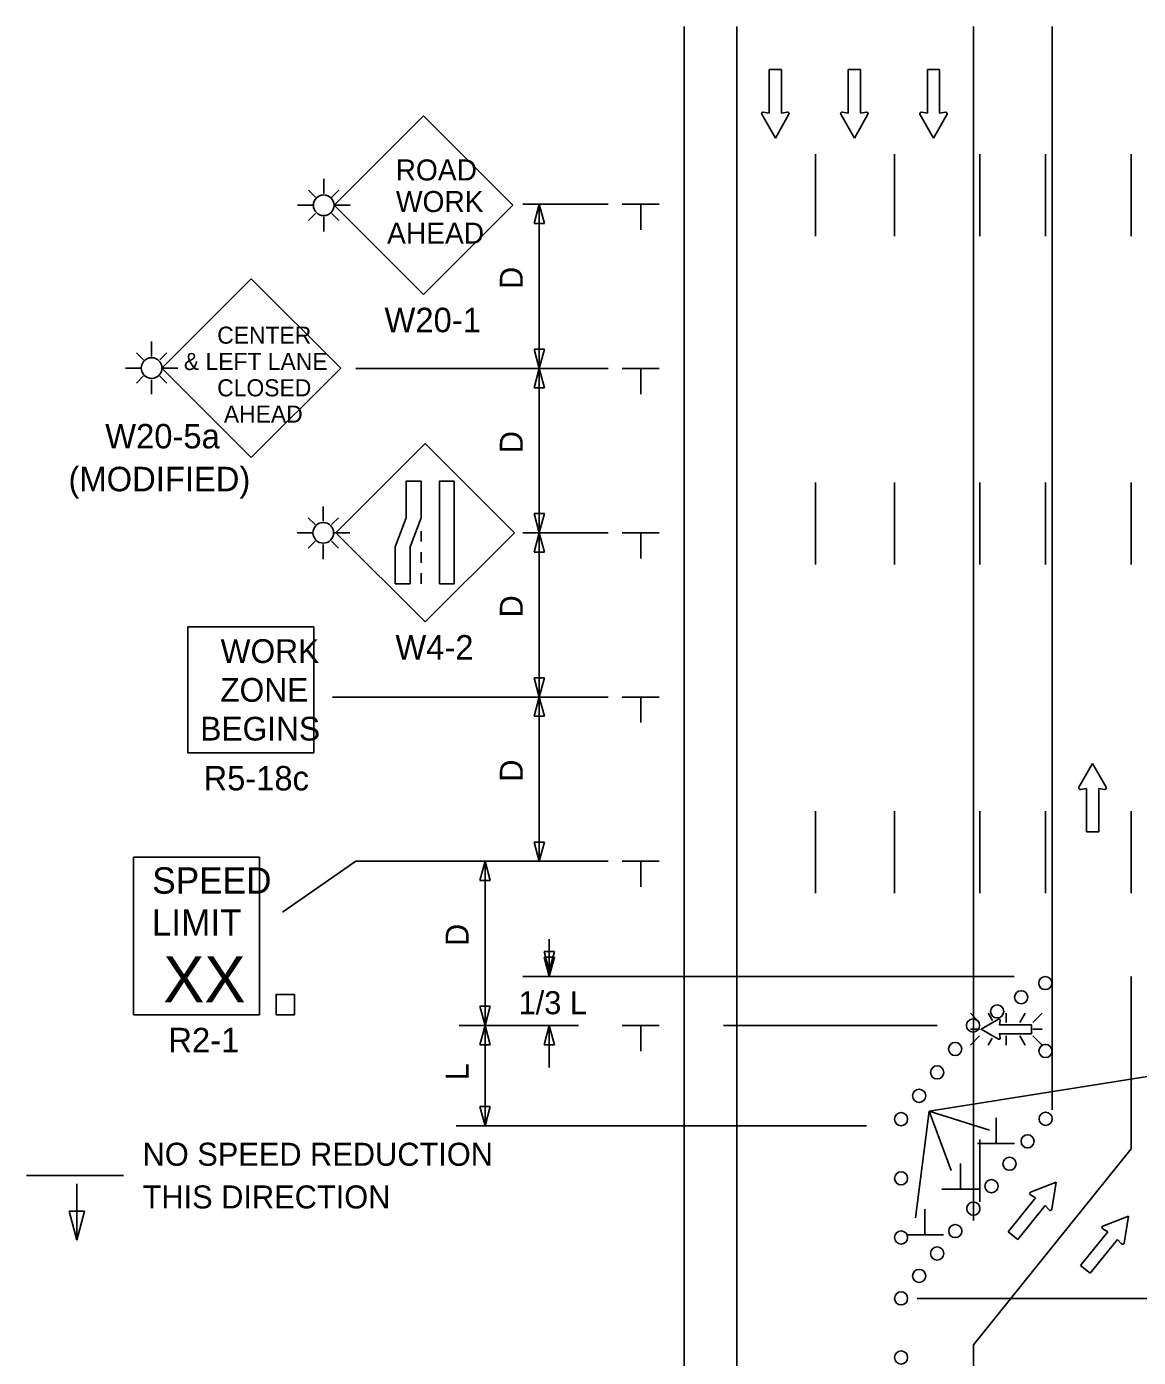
# Model space of a CAD drawing. Extents: x 16544 to 19504, y 5662 to 6922.
# Drawn here: x 16723.4 to 17061.7, y 6474.9 to 6880 of the extents above; entities that cross this region are included whole.
import ezdxf

# ---------------------------------------------------------------- set-up
doc = ezdxf.new("R2010")
doc.units = 0
for name, color, linetype in [('ALI_LEGAL_EX', 7, 'Continuous'), ('Level 3', 7, 'Continuous'), ('MT_SCRATCH_LEVEL_E', 7, 'Continuous'), ('PAVT_EDGE_EX', 7, 'Continuous'), ('TRAFFIC_SIGNS_PR', 7, 'Continuous'), ('TYPICAL_TEXT_DIMEN_PR', 7, 'Continuous')]:
    doc.layers.add(name, color=color, linetype=linetype)

msp = doc.modelspace()

# ---------------------------------------------------------------- linework, layer by layer
at = {"layer": 'ALI_LEGAL_EX'}
for points in [[(16963.46, 6841.23), (16963.46, 6816.23)], [(16987.46, 6841.23), (16987.46, 6816.23)], [(17013.46, 6841.23), (17013.46, 6816.23)], [(17033.46, 6841.23), (17033.46, 6816.23)], [(17059.46, 6841.23), (17059.46, 6816.23)], [(16963.46, 6741.23), (16963.46, 6716.23)], [(16987.46, 6741.23), (16987.46, 6716.23)], [(16987.46, 6741.23), (16987.46, 6716.23)], [(17013.46, 6741.23), (17013.46, 6716.23)], [(17013.46, 6741.23), (17013.46, 6716.23)], [(17033.46, 6741.23), (17033.46, 6716.23)], [(17033.46, 6741.23), (17033.46, 6716.23)], [(17059.46, 6741.23), (17059.46, 6716.23)], [(17059.46, 6741.23), (17059.46, 6716.23)], [(16963.46, 6641.23), (16963.46, 6616.23)], [(16987.46, 6641.23), (16987.46, 6616.23)], [(16987.46, 6641.23), (16987.46, 6616.23)], [(17013.46, 6641.23), (17013.46, 6616.23)], [(17013.46, 6641.23), (17013.46, 6616.23)], [(17033.46, 6641.23), (17033.46, 6616.23)], [(17033.46, 6641.23), (17033.46, 6616.23)], [(17059.46, 6641.23), (17059.46, 6616.23)], [(17059.46, 6641.23), (17059.46, 6616.23)], [(17013.46, 6541.23), (17013.46, 6522.22)], [(17013.46, 6541.23), (17013.46, 6524.21)]]:
    msp.add_lwpolyline(points, dxfattribs=at)
at = {"layer": 'Level 3'}
for p, q in [((16823.56, 6625.93), (16801.21, 6610.49)), ((16882.4, 6602.19), (16882.4, 6590.85)), ((16882.4, 6575.93), (16882.4, 6563.15))]:
    msp.add_line(p, q, dxfattribs=at)
at = {"layer": 'MT_SCRATCH_LEVEL_E'}
for p, q in [((16953.06, 6866.95), (16949.32, 6866.95)), ((16949.32, 6866.95), (16949.32, 6853.69)), ((16953.06, 6866.95), (16949.32, 6866.95)), ((16949.32, 6866.95), (16949.32, 6853.69)), ((16953.06, 6853.69), (16953.06, 6866.95)), ((16953.06, 6853.69), (16953.06, 6866.95)), ((16977.13, 6866.95), (16973.39, 6866.95)), ((16973.39, 6866.95), (16973.39, 6853.69)), ((16977.13, 6866.95), (16973.39, 6866.95)), ((16973.39, 6866.95), (16973.39, 6853.69)), ((16977.13, 6853.69), (16977.13, 6866.95)), ((16977.13, 6853.69), (16977.13, 6866.95)), ((17001.2, 6866.95), (16997.46, 6866.95)), ((16997.46, 6866.95), (16997.46, 6853.69)), ((17001.2, 6866.95), (16997.46, 6866.95)), ((16997.46, 6866.95), (16997.46, 6853.69)), ((17001.2, 6853.69), (17001.2, 6866.95)), ((17001.2, 6853.69), (17001.2, 6866.95)), ((16947.06, 6853.32), (16951.21, 6846.09)), ((16947.06, 6853.32), (16951.21, 6846.09)), ((16949.32, 6853.69), (16947.54, 6854.01)), ((16949.32, 6853.69), (16947.54, 6854.01)), ((16951.21, 6846.09), (16955.32, 6853.32)), ((16951.21, 6846.09), (16955.32, 6853.32)), ((16954.83, 6854.01), (16953.06, 6853.69)), ((16954.83, 6854.01), (16953.06, 6853.69)), ((16971.13, 6853.32), (16975.28, 6846.09)), ((16971.13, 6853.32), (16975.28, 6846.09)), ((16973.39, 6853.69), (16971.61, 6854.01)), ((16973.39, 6853.69), (16971.61, 6854.01)), ((16975.28, 6846.09), (16979.39, 6853.32)), ((16975.28, 6846.09), (16979.39, 6853.32)), ((16978.91, 6854.01), (16977.13, 6853.69)), ((16978.91, 6854.01), (16977.13, 6853.69)), ((16995.2, 6853.32), (16999.35, 6846.09)), ((16995.2, 6853.32), (16999.35, 6846.09)), ((16997.46, 6853.69), (16995.68, 6854.01)), ((16997.46, 6853.69), (16995.68, 6854.01)), ((16999.35, 6846.09), (17003.46, 6853.32)), ((16999.35, 6846.09), (17003.46, 6853.32)), ((17002.98, 6854.01), (17001.2, 6853.69)), ((17002.98, 6854.01), (17001.2, 6853.69)), ((17047.7, 6655.73), (17043.59, 6648.49)), ((17047.7, 6655.73), (17043.59, 6648.49)), ((17051.85, 6648.49), (17047.7, 6655.73)), ((17051.85, 6648.49), (17047.7, 6655.73)), ((17044.07, 6647.81), (17045.85, 6648.12)), ((17044.07, 6647.81), (17045.85, 6648.12)), ((17045.85, 6648.12), (17045.85, 6634.86)), ((17045.85, 6648.12), (17045.85, 6634.86)), ((17049.59, 6634.86), (17049.59, 6648.12)), ((17049.59, 6648.12), (17051.37, 6647.81)), ((17049.59, 6634.86), (17049.59, 6648.12)), ((17049.59, 6648.12), (17051.37, 6647.81)), ((17045.85, 6634.86), (17049.59, 6634.86)), ((17045.85, 6634.86), (17049.59, 6634.86)), ((17028.87, 6525.2), (17036.64, 6528.24)), ((17028.87, 6525.2), (17036.64, 6528.24)), ((17036.64, 6528.24), (17035.3, 6520.02)), ((17036.64, 6528.24), (17035.3, 6520.02)), ((17022.08, 6513.17), (17030.39, 6523.5)), ((17022.08, 6513.17), (17030.39, 6523.5)), ((17030.39, 6523.5), (17028.81, 6524.37)), ((17030.39, 6523.5), (17028.81, 6524.37)), ((17033.31, 6521.15), (17024.99, 6510.82)), ((17033.31, 6521.15), (17024.99, 6510.82)), ((17034.49, 6519.79), (17033.31, 6521.15)), ((17034.49, 6519.79), (17033.31, 6521.15)), ((17050.89, 6514.87), (17058.66, 6517.91)), ((17050.89, 6514.87), (17058.66, 6517.91)), ((17058.66, 6517.91), (17057.32, 6509.69)), ((17058.66, 6517.91), (17057.32, 6509.69)), ((17024.99, 6510.82), (17022.08, 6513.17)), ((17024.99, 6510.82), (17022.08, 6513.17)), ((17044.1, 6502.84), (17052.41, 6513.17)), ((17044.1, 6502.84), (17052.41, 6513.17)), ((17055.33, 6510.82), (17047.01, 6500.5)), ((17055.33, 6510.82), (17047.01, 6500.5)), ((17052.41, 6513.17), (17050.83, 6514.04)), ((17052.41, 6513.17), (17050.83, 6514.04)), ((17056.51, 6509.46), (17055.33, 6510.82)), ((17056.51, 6509.46), (17055.33, 6510.82)), ((17047.01, 6500.5), (17044.1, 6502.84)), ((17047.01, 6500.5), (17044.1, 6502.84))]:
    msp.add_line(p, q, dxfattribs=at)
for centre, start, end in [((16947.47, 6853.55), 80.0362, 209.7731), ((16947.47, 6853.55), 80.0362, 209.7731), ((16954.91, 6853.55), 330.4248, 99.9638), ((16954.91, 6853.55), 330.4248, 99.9638), ((16971.54, 6853.55), 80.0362, 209.7731), ((16971.54, 6853.55), 80.0362, 209.7731), ((16978.98, 6853.55), 330.4248, 99.9638), ((16978.98, 6853.55), 330.4248, 99.9638), ((16995.61, 6853.55), 80.0362, 209.7731), ((16995.61, 6853.55), 80.0362, 209.7731), ((17003.05, 6853.55), 330.4248, 99.9638), ((17003.05, 6853.55), 330.4248, 99.9638), ((17044, 6648.26), 150.4248, 279.9638), ((17044, 6648.26), 150.4248, 279.9638), ((17051.44, 6648.27), 260.0362, 29.7731), ((17051.44, 6648.27), 260.0362, 29.7731), ((17029.04, 6524.77), 111.3861, 241.123), ((17029.04, 6524.77), 111.3861, 241.123), ((17034.84, 6520.1), 221.1954, 350.7344), ((17034.84, 6520.1), 221.1954, 350.7344), ((17051.06, 6514.44), 111.3861, 241.123), ((17051.06, 6514.44), 111.3861, 241.123), ((17056.86, 6509.77), 221.1954, 350.7344), ((17056.86, 6509.77), 221.1954, 350.7344)]:
    msp.add_arc(centre, 0.463, start, end, dxfattribs=at)
at = {"layer": 'PAVT_EDGE_EX'}
for p, q in [((16923.46, 6880.02), (16923.46, 6074.05)), ((16939.46, 6880.02), (16939.46, 6074.05)), ((17011.46, 6880.02), (17011.46, 6516.57)), ((17035.46, 6880.02), (17035.46, 6550.27)), ((17011.46, 6794.72), (17011.46, 6522.22)), ((17035.46, 6794.72), (17035.46, 6552.57)), ((17059.46, 6590.85), (17059.46, 6538.35)), ((17011.46, 6478.73), (17059.46, 6538.35)), ((17011.46, 6478.73), (17011.46, 6277.01))]:
    msp.add_line(p, q, dxfattribs=at)
at = {"layer": 'TRAFFIC_SIGNS_PR'}
for p, q in [((16844.12, 6852.82), (16816.94, 6825.63)), ((16871.31, 6825.63), (16844.12, 6852.82)), ((16813.78, 6829.19), (16813.78, 6833.69)), ((16811.27, 6828.15), (16809.16, 6830.25)), ((16816.3, 6828.15), (16818.41, 6830.25)), ((16810.63, 6825.63), (16805.79, 6825.63)), ((16811.27, 6823.12), (16809.16, 6821.01)), ((16816.3, 6823.12), (16818.4, 6821.01)), ((16816.94, 6825.63), (16821.82, 6825.63)), ((16816.94, 6825.63), (16844.12, 6798.45)), ((16844.12, 6798.45), (16871.31, 6825.63)), ((16813.78, 6817.67), (16813.78, 6822.08)), ((16791.76, 6803.27), (16764.57, 6776.08)), ((16818.95, 6776.08), (16791.76, 6803.27)), ((16761.42, 6779.63), (16761.42, 6784.14)), ((16758.91, 6778.59), (16756.8, 6780.7)), ((16763.93, 6778.59), (16766.04, 6780.7)), ((16758.26, 6776.08), (16753.43, 6776.08)), ((16758.9, 6773.57), (16756.8, 6771.46)), ((16763.93, 6773.57), (16766.04, 6771.46)), ((16764.57, 6776.08), (16769.45, 6776.08)), ((16764.57, 6776.08), (16791.76, 6748.89)), ((16791.76, 6748.89), (16818.95, 6776.08)), ((16761.42, 6768.11), (16761.42, 6772.52)), ((16844.64, 6753.09), (16817.48, 6725.94)), ((16871.79, 6725.94), (16844.64, 6753.09)), ((16813.65, 6729.46), (16813.65, 6733.96)), ((16811.14, 6728.42), (16809.03, 6730.53)), ((16816.16, 6728.42), (16818.27, 6730.53)), ((16810.5, 6725.91), (16805.66, 6725.91)), ((16816.8, 6725.91), (16821.69, 6725.91)), ((16817.48, 6725.94), (16844.64, 6698.78)), ((16843.39, 6726.43), (16843.39, 6723.23)), ((16844.64, 6698.78), (16871.79, 6725.94)), ((16811.14, 6723.39), (16809.03, 6721.28)), ((16813.65, 6717.94), (16813.65, 6722.35)), ((16816.16, 6723.39), (16818.27, 6721.29)), ((16843.39, 6720.03), (16843.39, 6716.83)), ((16843.39, 6713.63), (16843.39, 6710.43)), ((16772.41, 6658.94), (16772.41, 6697.34)), ((16772.41, 6697.34), (16810.81, 6697.34)), ((16810.81, 6658.94), (16810.81, 6697.34)), ((16772.41, 6658.94), (16810.81, 6658.94)), ((16755.86, 6627.23), (16794.26, 6627.23)), ((16755.86, 6579.23), (16755.86, 6627.23)), ((16794.26, 6579.23), (16794.26, 6627.23)), ((16755.86, 6579.23), (16794.26, 6579.23)), ((17010.54, 6579.66), (17013.36, 6576.84)), ((17017.26, 6577.48), (17016, 6579.66)), ((17021.45, 6576.84), (17021.45, 6579.66)), ((17025.58, 6576.84), (17027.21, 6579.66)), ((17029.53, 6576.84), (17032.35, 6579.66)), ((17013.36, 6574.81), (17010.54, 6574.81)), ((17010.54, 6569.96), (17013.36, 6572.78)), ((17015.98, 6569.96), (17017.19, 6572.05)), ((17021.45, 6572.78), (17021.45, 6569.96)), ((17027.24, 6569.96), (17025.61, 6572.78)), ((17029.53, 6574.81), (17032.35, 6574.81)), ((17029.53, 6572.78), (17032.35, 6569.96))]:
    msp.add_line(p, q, dxfattribs=at)
for points in [[(16843.39, 6741.67), (16843.39, 6730.49), (16840.05, 6721.61), (16840.05, 6710.43), (16835.55, 6710.43), (16835.55, 6721.61), (16838.9, 6730.49), (16838.9, 6741.67)], [(16853.53, 6741.67), (16853.53, 6710.43), (16849.03, 6710.43), (16849.03, 6741.67)], [(16799.27, 6579.23), (16804.87, 6579.23), (16804.87, 6585.4), (16799.27, 6585.4)]]:
    msp.add_lwpolyline(points, close=True, dxfattribs=at)
for points in [[(17019.12, 6577.82), (17013.81, 6574.81), (17019.12, 6571.77)], [(17019.62, 6572.13), (17019.39, 6573.42), (17029.11, 6573.42), (17029.11, 6576.17), (17019.39, 6576.17), (17019.62, 6577.47)]]:
    msp.add_lwpolyline(points, dxfattribs=at)
for centre, radius in [((16813.78, 6825.63), 3.15), ((16761.42, 6776.08), 3.15), ((16813.65, 6725.91), 3.15), ((17033.35, 6588.85), 2), ((17033.35, 6588.85), 2), ((17026.02, 6584.54), 2), ((17018.69, 6580.23), 2), ((17011.36, 6575.93), 2), ((17005.94, 6568.79), 2), ((17033.4, 6568.18), 2), ((17000.45, 6561.67), 2), ((16994.95, 6554.54), 2), ((16989.46, 6547.41), 2), ((16989.46, 6547.41), 2), ((16989.46, 6547.41), 2), ((17033.46, 6547.51), 2), ((17027.96, 6540.68), 2), ((17022.46, 6533.85), 2), ((16989.46, 6529.41), 2), ((17016.96, 6527.02), 2), ((17011.46, 6520.19), 2), ((17005.96, 6513.36), 2), ((16989.46, 6511.41), 2), ((17000.46, 6506.53), 2), ((16994.96, 6499.7), 2), ((16989.46, 6492.87), 2), ((16989.46, 6474.87), 2)]:
    msp.add_circle(centre, radius, dxfattribs=at)
for centre, start, end in [((17019.28, 6577.53), 350.7308, 118.8916), ((17019.28, 6572.07), 241.4833, 9.9593)]:
    msp.add_arc(centre, 0.341, start, end, dxfattribs=at)
at = {"layer": 'TYPICAL_TEXT_DIMEN_PR'}
for p, q in [((16874.36, 6825.93), (16900.36, 6825.93)), ((16877.79, 6820.07), (16879.36, 6825.93)), ((16879.36, 6775.93), (16879.36, 6825.93)), ((16879.36, 6825.93), (16880.93, 6820.07)), ((16904.61, 6825.93), (16915.86, 6825.93)), ((16910.24, 6825.93), (16910.24, 6818.15)), ((16879.36, 6820.07), (16877.79, 6820.07)), ((16880.93, 6820.07), (16879.36, 6820.07)), ((16879.36, 6775.93), (16877.79, 6781.79)), ((16877.79, 6781.79), (16879.36, 6781.79)), ((16879.36, 6781.79), (16880.93, 6781.79)), ((16880.93, 6781.79), (16879.36, 6775.93)), ((16823.56, 6775.93), (16900.36, 6775.93)), ((16874.36, 6775.93), (16900.36, 6775.93)), ((16877.79, 6770.07), (16879.36, 6775.93)), ((16879.36, 6725.93), (16879.36, 6775.93)), ((16879.36, 6775.93), (16880.93, 6770.07)), ((16904.61, 6775.93), (16915.86, 6775.93)), ((16910.24, 6775.93), (16910.24, 6768.15)), ((16879.36, 6770.07), (16877.79, 6770.07)), ((16880.93, 6770.07), (16879.36, 6770.07)), ((16879.36, 6725.93), (16877.79, 6731.79)), ((16877.79, 6731.79), (16879.36, 6731.79)), ((16879.36, 6731.79), (16880.93, 6731.79)), ((16880.93, 6731.79), (16879.36, 6725.93)), ((16874.36, 6725.93), (16900.36, 6725.93)), ((16876.12, 6725.93), (16900.36, 6725.93)), ((16877.79, 6720.07), (16879.36, 6725.93)), ((16879.36, 6725.93), (16880.93, 6720.07)), ((16879.36, 6675.93), (16879.36, 6725.93)), ((16904.61, 6725.93), (16915.86, 6725.93)), ((16910.24, 6725.93), (16910.24, 6718.15)), ((16879.36, 6720.07), (16877.79, 6720.07)), ((16880.93, 6720.07), (16879.36, 6720.07)), ((16879.36, 6675.93), (16877.79, 6681.79)), ((16877.79, 6681.79), (16879.36, 6681.79)), ((16879.36, 6681.79), (16880.93, 6681.79)), ((16880.93, 6681.79), (16879.36, 6675.93)), ((16816.43, 6675.93), (16900.36, 6675.93)), ((16877.79, 6670.07), (16879.36, 6675.93)), ((16877.79, 6670.07), (16879.36, 6675.93)), ((16879.36, 6675.93), (16880.93, 6670.07)), ((16879.36, 6625.93), (16879.36, 6675.93)), ((16879.36, 6675.93), (16880.93, 6670.07)), ((16904.61, 6675.93), (16915.86, 6675.93)), ((16910.24, 6675.93), (16910.24, 6668.15)), ((16879.36, 6670.07), (16877.79, 6670.07)), ((16879.36, 6670.07), (16877.79, 6670.07)), ((16880.93, 6670.07), (16879.36, 6670.07)), ((16880.93, 6670.07), (16879.36, 6670.07)), ((16879.36, 6625.93), (16877.79, 6631.79)), ((16877.79, 6631.79), (16879.36, 6631.79)), ((16879.36, 6631.79), (16880.93, 6631.79)), ((16880.93, 6631.79), (16879.36, 6625.93)), ((16823.56, 6625.93), (16900.36, 6625.93)), ((16861.31, 6620.07), (16862.88, 6625.93)), ((16862.88, 6575.93), (16862.88, 6625.93)), ((16862.88, 6625.93), (16864.45, 6620.07)), ((16874.36, 6625.93), (16900.36, 6625.93)), ((16904.61, 6625.93), (16915.86, 6625.93)), ((16910.24, 6625.93), (16910.24, 6618.15)), ((16862.88, 6620.07), (16861.31, 6620.07)), ((16864.45, 6620.07), (16862.88, 6620.07)), ((16882.4, 6592.58), (16880.83, 6598.44)), ((16880.83, 6598.44), (16882.4, 6598.44)), ((16882.4, 6590.85), (16880.83, 6596.72)), ((16880.83, 6596.72), (16882.4, 6596.72)), ((16882.4, 6598.44), (16883.97, 6598.44)), ((16883.97, 6598.44), (16882.4, 6592.58)), ((16882.4, 6596.72), (16883.97, 6596.72)), ((16883.97, 6596.72), (16882.4, 6590.85)), ((16874.36, 6590.85), (17023.87, 6590.85)), ((16862.88, 6575.93), (16861.31, 6581.79)), ((16861.31, 6581.79), (16862.88, 6581.79)), ((16862.88, 6581.79), (16864.45, 6581.79)), ((16864.45, 6581.79), (16862.88, 6575.93)), ((16891.35, 6575.93), (16855, 6575.93)), ((16861.31, 6570.07), (16862.88, 6575.93)), ((16862.88, 6545.4), (16862.88, 6575.93)), ((16862.88, 6575.93), (16864.45, 6570.07)), ((16880.83, 6570.07), (16882.4, 6575.93)), ((16882.4, 6575.93), (16883.97, 6570.07)), ((16904.61, 6575.93), (16915.86, 6575.93)), ((16910.24, 6575.93), (16910.24, 6568.15)), ((17000.44, 6575.93), (16935.41, 6575.93)), ((17139.51, 6572.32), (16997.97, 6549.9)), ((16862.88, 6570.07), (16861.31, 6570.07)), ((16864.45, 6570.07), (16862.88, 6570.07)), ((16882.4, 6570.07), (16880.83, 6570.07)), ((16883.97, 6570.07), (16882.4, 6570.07)), ((16862.88, 6545.4), (16861.31, 6551.26)), ((16861.31, 6551.26), (16862.88, 6551.26)), ((16862.88, 6551.26), (16864.45, 6551.26)), ((16864.45, 6551.26), (16862.88, 6545.4)), ((16993.88, 6517.37), (16997.97, 6549.9)), ((16997.97, 6549.9), (17004.69, 6531.83)), ((16997.97, 6549.9), (17016.35, 6544.09)), ((17018.37, 6540.05), (17018.37, 6547.83)), ((16854.1, 6545.4), (16978.94, 6545.4)), ((17023.99, 6540.05), (17012.74, 6540.05)), ((17007.54, 6526.12), (17007.54, 6533.9)), ((16752.83, 6530.24), (16723.39, 6530.24)), ((16738.66, 6527.74), (16738.66, 6510.62)), ((17013.16, 6526.12), (17001.91, 6526.12)), ((16738.66, 6519.41), (16736.3, 6519.41)), ((16736.3, 6519.41), (16738.66, 6510.62)), ((16738.66, 6510.62), (16741.01, 6519.41)), ((16741.01, 6519.41), (16738.66, 6519.41)), ((16996.71, 6512.19), (16996.71, 6519.98)), ((17002.33, 6512.19), (16991.08, 6512.19)), ((17172.46, 6492.87), (16994.34, 6492.87))]:
    msp.add_line(p, q, dxfattribs=at)

# ---------------------------------------------------------------- texts
at = {"layer": 'TRAFFIC_SIGNS_PR'}
for s, height, p in [('ROAD', 6.408, (16835.66, 6833.18)), ('WORK', 6.408, (16835.76, 6823.57)), ('AHEAD', 6.408, (16833.07, 6813.95)), ('W20-1', 7.449, (16832.28, 6786.99)), ('CENTER', 5.206, (16781.38, 6783.49)), ('& LEFT LANE', 5.2065, (16771.24, 6775.48)), ('CLOSED', 5.206, (16781.38, 6767.47)), ('AHEAD', 5.206, (16783.41, 6759.46)), ('W20-5a', 7.449, (16747.29, 6751.62)), ('(MODIFIED)', 7.449, (16736.13, 6738.57)), ('WORK', 7.217, (16782.41, 6686.31)), ('W4-2', 7.44, (16835.6, 6687.35)), ('ZONE', 7.217, (16782.29, 6674.5)), ('BEGINS', 7.217, (16776.22, 6662.69)), ('R5-18c', 7.44, (16777.22, 6647.5)), ('SPEED', 8, (16761.62, 6616.09)), ('LIMIT', 8, (16761.46, 6603.29)), ('XX', 14.031, (16764.97, 6582.99)), ('R2-1', 7.44, (16766.53, 6567.79))]:
    msp.add_text(s, height=height, dxfattribs=at).set_placement(p)
at = {"layer": 'TYPICAL_TEXT_DIMEN_PR'}
for s, p in [('D', (16874.36, 6800.15)), ('D', (16874.36, 6750.15)), ('D', (16874.36, 6700.15)), ('D', (16874.36, 6650.15)), ('D', (16874.36, 6650.15)), ('D', (16857.89, 6600.15)), ('L', (16857.89, 6559.26))]:
    msp.add_text(s, height=7, rotation=90, dxfattribs=at).set_placement(p)
for s, p in [('1/3 L', (16873.08, 6579.38)), ('NO SPEED REDUCTION', (16758.67, 6533.25)), ('THIS DIRECTION', (16758.67, 6520.25))]:
    msp.add_text(s, height=7, dxfattribs=at).set_placement(p)

doc.saveas('drawing.dxf')
